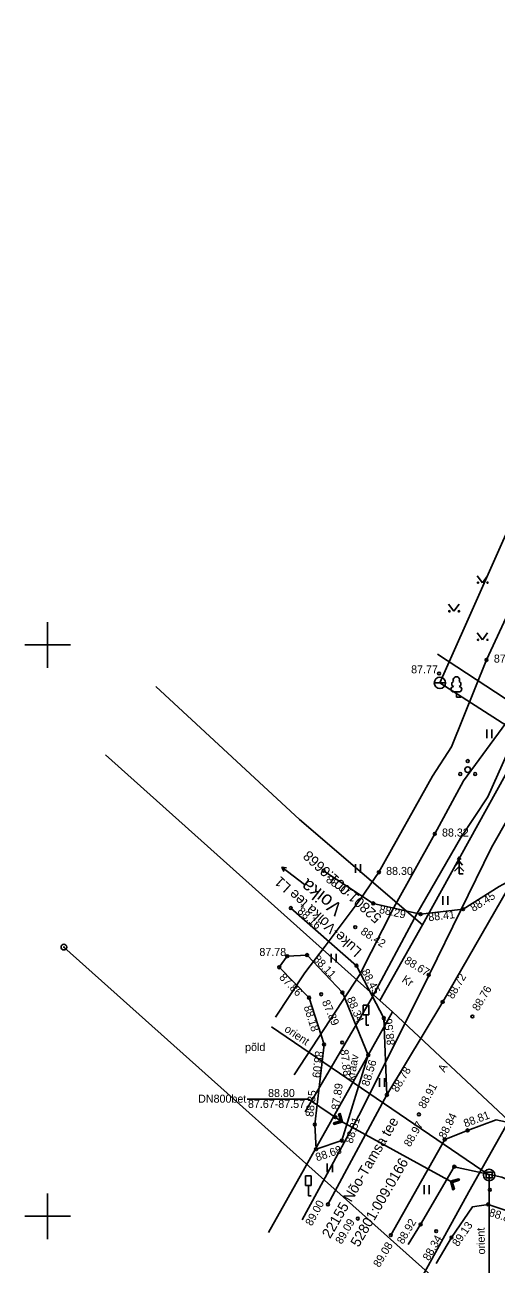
# Model space of a CAD drawing. Extents: x 648748 to 649126, y 6457789 to 6458252.
# Drawn here: x 648748 to 648789.3, y 6457945.8 to 6458054.3 of the extents above; entities that cross this region are included whole.
import ezdxf

# ---------------------------------------------------------------- set-up
doc = ezdxf.new("R2010")
doc.units = 0
for name, color, linetype in [('DKAEV', 7, 'Continuous'), ('DTRASS', 7, 'Continuous'), ('HALJASTUS', 7, 'Continuous'), ('KORGUS-EH2000', 7, 'Continuous'), ('KPOHULIIN', 7, 'Continuous'), ('LIIKLUS', 7, 'Continuous'), ('PIIR', 7, 'Continuous'), ('POST', 7, 'Continuous'), ('PUU', 7, 'Continuous'), ('SITRASS', 7, 'Continuous'), ('TEE', 7, 'Continuous'), ('TRUUP', 7, 'Continuous'), ('VEEKOGU', 7, 'Continuous'), ('VKAEV', 7, 'Continuous'), ('VORK', 7, 'Continuous'), ('VTRASS', 7, 'Continuous')]:
    doc.layers.add(name, color=color, linetype=linetype)

msp = doc.modelspace()

# ---------------------------------------------------------------- linework, layer by layer
at = {"layer": 'DKAEV'}
for p, q in [((648788.39, 6457953.36), (648788.39, 6457953.86)), ((648788.39, 6457953.86), (648788.89, 6457953.86)), ((648788.89, 6457953.36), (648788.39, 6457953.36)), ((648788.89, 6457953.86), (648788.89, 6457953.36))]:
    msp.add_line(p, q, dxfattribs=at)
msp.add_circle((648788.64, 6457953.61), 0.5, dxfattribs=at)
at = {"layer": 'DTRASS'}
for q in [(648769.6, 6457966.59), (648788.64, 6457943.27)]:
    msp.add_line((648788.64, 6457953.61), q, dxfattribs=at)
at = {"layer": 'HALJASTUS'}
for p, q in [((648787.59, 6458006.05), (648788.06, 6458005.44)), ((648788.06, 6458005.44), (648788.5, 6458006.05)), ((648785.09, 6458003.55), (648785.56, 6458002.94)), ((648785.56, 6458002.94), (648786, 6458003.55)), ((648787.59, 6458001.05), (648788.06, 6458000.44)), ((648788.06, 6458000.44), (648788.5, 6458001.05)), ((648784.11, 6457999.19), (648796.89, 6457990.82)), ((648788.42, 6457992.59), (648788.42, 6457991.83)), ((648788.87, 6457992.59), (648788.87, 6457991.83)), ((648776.93, 6457980.82), (648776.93, 6457980.06)), ((648777.39, 6457980.82), (648777.39, 6457980.06)), ((648784.58, 6457978.02), (648784.58, 6457977.26)), ((648785.03, 6457978.02), (648785.03, 6457977.26)), ((648774.81, 6457972.96), (648774.81, 6457972.2)), ((648775.26, 6457972.96), (648775.26, 6457972.2)), ((648779.03, 6457962.1), (648779.03, 6457961.34)), ((648779.49, 6457962.1), (648779.49, 6457961.34)), ((648774.46, 6457954.62), (648774.46, 6457953.86)), ((648774.92, 6457954.62), (648774.92, 6457953.86)), ((648782.95, 6457952.71), (648782.95, 6457951.95)), ((648783.4, 6457952.71), (648783.4, 6457951.95))]:
    msp.add_line(p, q, dxfattribs=at)
for centre in [(648787.66, 6458005.44), (648788.49, 6458005.44), (648785.16, 6458002.94), (648785.99, 6458002.94), (648787.66, 6458000.44), (648788.49, 6458000.44)]:
    msp.add_circle(centre, 0.055, dxfattribs=at)
at = {"layer": 'KORGUS-EH2000'}
for centre in [(648788.41, 6457998.68), (648784.25, 6457997.49), (648783.88, 6457983.46), (648774.15, 6457980.24), (648778.99, 6457980.1), (648778.5, 6457977.38), (648771.28, 6457976.97), (648782.64, 6457976.44), (648786.35, 6457976.88), (648776.92, 6457975.3), (648770.97, 6457972.76), (648772.7, 6457972.86), (648770.27, 6457971.79), (648777.03, 6457971.93), (648783.35, 6457971.12), (648775.79, 6457969.57), (648772.88, 6457969.13), (648773.94, 6457969.43), (648784.57, 6457968.76), (648779.42, 6457967.35), (648787.17, 6457967.48), (648775.77, 6457965.21), (648774.19, 6457965.03), (648778.06, 6457964.11), (648779.69, 6457960.62), (648775.19, 6457958.67), (648782.49, 6457958.92), (648773.38, 6457958.02), (648775.74, 6457956.62), (648784.75, 6457956.72), (648786.75, 6457957.52), (648773.49, 6457955.87), (648785.59, 6457954.34), (648788.7, 6457952.31), (648774.53, 6457951.04), (648788.55, 6457951.04), (648777.14, 6457949.8), (648782.64, 6457949.28), (648780.03, 6457948.35), (648784, 6457948.7), (648785.34, 6457948.14)]:
    msp.add_circle(centre, 0.125, dxfattribs=at)
at = {"layer": 'KPOHULIIN'}
msp.add_line((648751.42, 6457973.56), (648811.64, 6457919.76), dxfattribs=at)
at = {"layer": 'LIIKLUS'}
for points in [[(648777.62, 6457968.48), (648777.62, 6457967.63)], [(648778.12, 6457968.48), (648777.62, 6457968.48)], [(648778.12, 6457967.63), (648777.62, 6457967.63)], [(648777.87, 6457967.63), (648777.87, 6457966.73)], [(648778.12, 6457968.48), (648778.12, 6457967.63)], [(648778.12, 6457966.73), (648777.87, 6457966.73)], [(648772.57, 6457953.54), (648772.57, 6457952.69)], [(648773.07, 6457953.54), (648772.57, 6457953.54)], [(648773.07, 6457953.54), (648773.07, 6457952.69)], [(648773.07, 6457952.69), (648772.57, 6457952.69)], [(648772.82, 6457952.69), (648772.82, 6457951.79)], [(648773.07, 6457951.79), (648772.82, 6457951.79)]]:
    msp.add_lwpolyline(points, dxfattribs=at)
at = {"layer": 'PIIR'}
for p, q in [((648772.05, 6457984.72), (648759.46, 6457996.37)), ((648793.25, 6457994.41), (648782.79, 6457975.49)), ((648779.08, 6457968.88), (648755.06, 6457990.39)), ((648782.79, 6457975.49), (648772.05, 6457984.72)), ((648779.08, 6457968.88), (648782.79, 6457975.49)), ((648780.18, 6457967.9), (648779.08, 6457968.88)), ((648769.34, 6457948.58), (648780.18, 6457967.9)), ((648790.36, 6457958.35), (648780.18, 6457967.9)), ((648786.87, 6457952.13), (648790.36, 6457958.35)), ((648778.84, 6457937.61), (648786.87, 6457952.13))]:
    msp.add_line(p, q, dxfattribs=at)
at = {"layer": 'POST'}
for radius in [0.25, 0.0234]:
    msp.add_circle((648751.42, 6457973.56), radius, dxfattribs=at)
at = {"layer": 'PUU'}
for p, q in [((648786.01, 6457995.88), (648785.53, 6457995.88)), ((648785.77, 6457995.41), (648785.77, 6457995.88)), ((648786.15, 6457995.41), (648785.77, 6457995.41)), ((648786.01, 6457980.61), (648785.61, 6457980.21)), ((648786.01, 6457981.06), (648785.71, 6457980.71)), ((648786.01, 6457981.46), (648785.86, 6457981.21)), ((648786.16, 6457981.21), (648786.01, 6457981.46)), ((648786.01, 6457981.46), (648786.01, 6457979.96)), ((648786.31, 6457980.71), (648786.01, 6457981.06)), ((648786.41, 6457980.21), (648786.01, 6457980.61)), ((648786.37, 6457979.96), (648786.01, 6457979.96))]:
    msp.add_line(p, q, dxfattribs=at)
for centre, radius in [((648786.76, 6457989.08), 0.25), ((648786.76, 6457989.83), 0.125), ((648786.11, 6457988.7), 0.125), ((648787.41, 6457988.7), 0.125)]:
    msp.add_circle(centre, radius, dxfattribs=at)
for centre, radius, start, end in [((648785.6, 6457996.58), 0.233, 109.022, 253.142), ((648785.77, 6457996.93), 0.277, 332.58, 207.42), ((648785.94, 6457996.58), 0.233, 286.851, 70.986), ((648785.53, 6457996.12), 0.238, 90.002, 269.395), ((648786, 6457996.12), 0.238, 270.605, 89.998)]:
    msp.add_arc(centre, radius, start, end, dxfattribs=at)
at = {"layer": 'SITRASS'}
for points in [[(648838.18, 6458075.61), (648836.35, 6458076.52), (648834.03, 6458074.85), (648828.84, 6458070.08), (648823.37, 6458063.8), (648815.04, 6458050.91), (648808.67, 6458038.59), (648805.57, 6458032.71), (648798.85, 6458019.32), (648793.36, 6458009.37), (648788.41, 6457998.68), (648785.35, 6457991.07), (648783.69, 6457988.51), (648778.99, 6457980.1), (648777.34, 6457977.72), (648774.3, 6457973.65), (648772.51, 6457971.29), (648769.94, 6457967.43)], [(648840.7, 6458076.04), (648840.21, 6458074.52), (648835.99, 6458066.48), (648829.45, 6458054.74), (648823.39, 6458043.34), (648816.2, 6458031.07), (648810.1, 6458020.65), (648803.23, 6458008.29), (648797.37, 6457997.81), (648791.83, 6457987.5), (648788.85, 6457982.27), (648783.41, 6457971.18), (648777.4, 6457959.15), (648772.28, 6457949.69)], [(648771.56, 6457962.37), (648777.32, 6457971.17), (648780.29, 6457977.01), (648783.88, 6457983.46), (648786.39, 6457988.11), (648790.09, 6457993.16), (648795.13, 6458001.6), (648799.02, 6458008.18), (648807.6, 6458023.19), (648816.81, 6458039.67), (648823.72, 6458052.09), (648829.84, 6458063.34), (648833.46, 6458070), (648835.84, 6458074.5), (648836.93, 6458074.75), (648838.18, 6458075.61)], [(648772.53, 6457959.14), (648778.31, 6457968.99), (648782.3, 6457976.47), (648786.13, 6457983.09), (648788.53, 6457986.69), (648790.27, 6457990.62), (648793.73, 6457995.08), (648800.38, 6458006.93), (648808.98, 6458022.03), (648818.07, 6458038.43), (648824.93, 6458050.59), (648831.03, 6458061.41), (648834.79, 6458068.89), (648838.18, 6458075.61), (648839.48, 6458073.45), (648841.57, 6458071.26), (648846.87, 6458065.92), (648848.75, 6458063.39)]]:
    msp.add_lwpolyline(points, dxfattribs=at)
at = {"layer": 'TEE'}
for p in [(648772.48, 6457979.03), (648770.66, 6457980.18), (648770.91, 6457980.5)]:
    msp.add_line(p, (648770.5, 6457980.56), dxfattribs=at)
for points in [[(648844.3, 6458074.59), (648841.57, 6458069.96), (648835.93, 6458060.04), (648830.01, 6458049.68), (648824.32, 6458039.38), (648818.36, 6458028.96), (648812.61, 6458018.63), (648806.66, 6458008.28), (648800.57, 6457997.47), (648794.38, 6457986.28), (648790.81, 6457979.57), (648784.57, 6457968.76), (648779.69, 6457960.62), (648774.53, 6457951.04)], [(648790.81, 6457979.57), (648789.51, 6457978.85), (648786.35, 6457976.88), (648782.64, 6457976.44), (648778.5, 6457977.38), (648774.15, 6457980.24)], [(648771.28, 6457976.97), (648777.03, 6457971.93), (648779.42, 6457967.35), (648779.69, 6457960.62)], [(648812.41, 6457940.36), (648808.54, 6457944.02), (648800.05, 6457951.25), (648791.29, 6457958.01), (648789.24, 6457958.44), (648786.75, 6457957.52), (648784.75, 6457956.72)], [(648780.03, 6457948.35), (648784.75, 6457956.72)]]:
    msp.add_lwpolyline(points, dxfattribs=at)
at = {"layer": 'TRUUP'}
for p, q in [((648775.45, 6457958.96), (648775.59, 6457959)), ((648775.63, 6457958.35), (648775.45, 6457958.96)), ((648775.46, 6457958.96), (648775.61, 6457958.93)), ((648775.46, 6457958.93), (648775.62, 6457958.9)), ((648775.47, 6457958.9), (648775.63, 6457958.87)), ((648775.48, 6457958.88), (648775.64, 6457958.85)), ((648775.49, 6457958.85), (648775.64, 6457958.82)), ((648775.5, 6457958.98), (648775.61, 6457958.96)), ((648775.5, 6457958.82), (648775.65, 6457958.79)), ((648775.5, 6457958.8), (648775.66, 6457958.77)), ((648775.72, 6457958.3), (648775.52, 6457958.98)), ((648775.55, 6457958.99), (648775.6, 6457958.98)), ((648775.81, 6457958.26), (648775.59, 6457959)), ((648775.02, 6457958.17), (648775.63, 6457958.35)), ((648775.02, 6457958.17), (648775.06, 6457958.04)), ((648775.02, 6457958.17), (648775.33, 6457958.12)), ((648775.03, 6457958.15), (648775.28, 6457958.1)), ((648775.04, 6457958.11), (648775.72, 6457958.3)), ((648775.04, 6457958.12), (648775.22, 6457958.09)), ((648775.05, 6457958.09), (648775.17, 6457958.07)), ((648775.05, 6457958.07), (648775.12, 6457958.05)), ((648775.06, 6457958.04), (648775.81, 6457958.26)), ((648775.07, 6457958.19), (648775.38, 6457958.13)), ((648775.13, 6457958.2), (648775.44, 6457958.15)), ((648775.18, 6457958.22), (648775.49, 6457958.16)), ((648775.23, 6457958.24), (648775.54, 6457958.18)), ((648775.29, 6457958.25), (648775.6, 6457958.19)), ((648775.34, 6457958.27), (648775.65, 6457958.21)), ((648775.39, 6457958.28), (648775.7, 6457958.22)), ((648775.45, 6457958.3), (648775.76, 6457958.24)), ((648775.5, 6457958.31), (648775.81, 6457958.26)), ((648775.51, 6457958.77), (648775.67, 6457958.74)), ((648775.52, 6457958.74), (648775.68, 6457958.71)), ((648775.53, 6457958.72), (648775.68, 6457958.69)), ((648775.53, 6457958.69), (648775.69, 6457958.66)), ((648775.54, 6457958.66), (648775.7, 6457958.63)), ((648775.55, 6457958.63), (648775.71, 6457958.61)), ((648775.55, 6457958.33), (648775.8, 6457958.28)), ((648775.56, 6457958.61), (648775.72, 6457958.58)), ((648775.57, 6457958.58), (648775.72, 6457958.55)), ((648775.57, 6457958.55), (648775.73, 6457958.52)), ((648775.58, 6457958.53), (648775.74, 6457958.5)), ((648775.59, 6457958.5), (648775.75, 6457958.47)), ((648775.6, 6457958.47), (648775.75, 6457958.44)), ((648775.6, 6457958.45), (648775.76, 6457958.42)), ((648775.61, 6457958.42), (648775.77, 6457958.39)), ((648775.61, 6457958.34), (648775.79, 6457958.31)), ((648775.62, 6457958.39), (648775.78, 6457958.36)), ((648775.63, 6457958.37), (648775.79, 6457958.34)), ((648775.72, 6457958.3), (648785.34, 6457953.02)), ((648785.99, 6457953.29), (648785.25, 6457953.07)), ((648785.25, 6457953.07), (648785.46, 6457952.32)), ((648785.56, 6457953.01), (648785.25, 6457953.07)), ((648785.5, 6457953), (648785.26, 6457953.04)), ((648785.45, 6457952.98), (648785.26, 6457953.02)), ((648785.43, 6457952.96), (648785.27, 6457952.99)), ((648785.44, 6457952.93), (648785.28, 6457952.96)), ((648785.44, 6457952.91), (648785.29, 6457952.93)), ((648785.45, 6457952.88), (648785.29, 6457952.91)), ((648785.61, 6457953.03), (648785.3, 6457953.08)), ((648785.46, 6457952.85), (648785.3, 6457952.88)), ((648785.47, 6457952.82), (648785.31, 6457952.85)), ((648785.47, 6457952.8), (648785.32, 6457952.83)), ((648785.48, 6457952.77), (648785.33, 6457952.8)), ((648785.49, 6457952.74), (648785.33, 6457952.77)), ((648786.01, 6457953.22), (648785.34, 6457953.02)), ((648785.34, 6457953.02), (648785.53, 6457952.34)), ((648785.5, 6457952.72), (648785.34, 6457952.75)), ((648785.66, 6457953.04), (648785.35, 6457953.1)), ((648785.51, 6457952.69), (648785.35, 6457952.72)), ((648785.51, 6457952.66), (648785.36, 6457952.69)), ((648785.52, 6457952.64), (648785.36, 6457952.67)), ((648785.53, 6457952.61), (648785.37, 6457952.64)), ((648785.54, 6457952.58), (648785.38, 6457952.61)), ((648785.55, 6457952.56), (648785.39, 6457952.59)), ((648785.55, 6457952.53), (648785.4, 6457952.56)), ((648785.56, 6457952.5), (648785.4, 6457952.53)), ((648785.72, 6457953.06), (648785.41, 6457953.12)), ((648785.57, 6457952.48), (648785.41, 6457952.5)), ((648786.03, 6457953.15), (648785.42, 6457952.97)), ((648785.42, 6457952.97), (648785.6, 6457952.36)), ((648785.58, 6457952.45), (648785.42, 6457952.48)), ((648785.58, 6457952.42), (648785.43, 6457952.45)), ((648785.59, 6457952.39), (648785.43, 6457952.42)), ((648785.6, 6457952.37), (648785.44, 6457952.4)), ((648785.56, 6457952.35), (648785.45, 6457952.37)), ((648785.77, 6457953.07), (648785.46, 6457953.13)), ((648785.6, 6457952.36), (648785.46, 6457952.32)), ((648785.51, 6457952.33), (648785.46, 6457952.34)), ((648785.82, 6457953.09), (648785.51, 6457953.15)), ((648785.88, 6457953.1), (648785.57, 6457953.16)), ((648785.93, 6457953.12), (648785.62, 6457953.18)), ((648785.98, 6457953.14), (648785.67, 6457953.19)), ((648786.03, 6457953.15), (648785.73, 6457953.21)), ((648786.03, 6457953.18), (648785.78, 6457953.22)), ((648786.02, 6457953.21), (648785.83, 6457953.24)), ((648786.01, 6457953.23), (648785.89, 6457953.26)), ((648786, 6457953.26), (648785.94, 6457953.27)), ((648786.03, 6457953.15), (648785.99, 6457953.29))]:
    msp.add_line(p, q, dxfattribs=at)
msp.add_lwpolyline([(648775.72, 6457958.3), (648772.84, 6457960.24), (648767.47, 6457960.24)], dxfattribs=at)
at = {"layer": 'VEEKOGU'}
for points in [[(648770.27, 6457971.79), (648770.97, 6457972.76), (648772.7, 6457972.86), (648775.79, 6457969.57), (648778.06, 6457964.11), (648775.74, 6457956.62), (648773.49, 6457955.87), (648773.38, 6457958.02), (648774.19, 6457965.03), (648772.88, 6457969.13), (648770.27, 6457971.79)], [(648781.55, 6457947.52), (648782.64, 6457949.28), (648785.59, 6457954.34), (648789.76, 6457953.43), (648797.17, 6457950.22), (648804.11, 6457946.85), (648805.16, 6457945.52), (648804.61, 6457945.14), (648796.89, 6457948.27), (648788.55, 6457951.04), (648787.17, 6457950.82), (648785.34, 6457948.14), (648784.01, 6457945.88)]]:
    msp.add_lwpolyline(points, dxfattribs=at)
at = {"layer": 'VKAEV'}
msp.add_line((648783.83, 6457996.67), (648784.83, 6457996.67), dxfattribs=at)
msp.add_circle((648784.33, 6457996.67), 0.5, dxfattribs=at)
at = {"layer": 'VORK'}
for p, q in [((648750, 6458002), (648750, 6457998)), ((648748, 6458000), (648752, 6458000)), ((648750, 6457952), (648750, 6457948)), ((648748, 6457950), (648752, 6457950))]:
    msp.add_line(p, q, dxfattribs=at)
at = {"layer": 'VTRASS'}
for p, q in [((648818.87, 6458074.61), (648784.33, 6457996.67)), ((648784.33, 6457996.67), (648805, 6457983.36))]:
    msp.add_line(p, q, dxfattribs=at)

# ---------------------------------------------------------------- texts
at = {"layer": 'DTRASS'}
for rotation, p in [(326.1395, (648770.66, 6457966.23)), (91.3542, (648788.29, 6457946.67))]:
    msp.add_text('orient', height=0.7, rotation=rotation, dxfattribs=at).set_placement(p)
at = {"layer": 'HALJASTUS'}
msp.add_text('põld', height=0.7, dxfattribs=at).set_placement((648767.28, 6457964.46))
at = {"layer": 'KORGUS-EH2000'}
for s, p in [(' 87.92', (648788.79, 6457998.45)), (' 87.77', (648781.55, 6457997.51)), (' 88.32', (648784.25, 6457983.23)), (' 88.30', (648779.36, 6457979.87)), (' 87.78', (648768.27, 6457972.78))]:
    msp.add_text(s, height=0.7, dxfattribs=at).set_placement(p)
for s, rotation, p in [(' 88.07', 326.6849, (648774.08, 6457979.45)), (' 88.45', 32.0568, (648787.04, 6457976.48)), (' 88.29', 347.309, (648778.71, 6457976.61)), (' 88.16', 318.7714, (648771.61, 6457976.78)), (' 88.41', 6.637, (648783.09, 6457975.79)), (' 88.42', 327.0037, (648777.11, 6457974.9)), (' 88.11', 313.2448, (648773.02, 6457972.65)), (' 88.67', 328.3177, (648780.93, 6457972.34)), (' 87.86', 314.3889, (648770.03, 6457971.04)), (' 88.45', 297.6142, (648777.32, 6457971.66)), (' 88.72', 60.0156, (648785.36, 6457968.73)), (' 88.76', 59.3075, (648787.56, 6457967.68)), (' 87.89', 293.3902, (648773.88, 6457969)), (' 88.34', 292.5801, (648776.07, 6457969.29)), (' 88.18', 287.8038, (648772.32, 6457968.57)), (' 88.56', 96.5778, (648780.43, 6457964.75)), (' 88.09', 263.4004, (648773.45, 6457964.75)), (' 87.88', 276.7467, (648775.58, 6457964.82)), (' 88.56', 72.7667, (648778.03, 6457961.08)), (' 88.78', 59.0617, (648780.49, 6457960.58)), (' 88.35', 83.4004, (648773.22, 6457958.41)), (' 87.89', 81.8215, (648775.47, 6457959.01)), (' 88.91', 61.3185, (648782.87, 6457959.13)), (' 88.84', 63.0333, (648784.66, 6457956.49)), (' 88.81', 20.3207, (648786.31, 6457957.68)), (' 88.81', 72.7667, (648776.59, 6457956.07)), (' 88.97', 59.8445, (648781.59, 6457955.79)), (' 88.68', 18.5132, (648773.33, 6457954.72)), (' 89.00', 61.6686, (648772.99, 6457948.87)), (' 88.88', 341.5972, (648788.32, 6457950.14)), (' 89.09', 59.4201, (648775.59, 6457947.28)), (' 88.92', 59.7046, (648780.98, 6457947.28)), (' 89.13', 55.7282, (648785.77, 6457947.08)), (' 88.34', 60.2812, (648783.25, 6457945.83)), (' 89.08', 58.9436, (648778.9, 6457945.25))]:
    msp.add_text(s, height=0.7, rotation=rotation, dxfattribs=at).set_placement(p)
at = {"layer": 'PIIR'}
for s, rotation, p in [('52801:001:0668', 137.7085, (648779.3, 6457976.22)), ('Luke-Voika tee L1', 137.7085, (648777.55, 6457973.28)), ('22155 Nõo-Tamsa tee', 59.7525, (648774.72, 6457948)), ('52801:009:0166', 59.7525, (648777.22, 6457947.24))]:
    msp.add_text(s, height=0.9, rotation=rotation, dxfattribs=at).set_placement(p)
at = {"layer": 'TEE'}
for s, height, rotation, p in [('Voika ', 1.2, 141.9672, (648775.9, 6457977.14)), ('Kr', 0.7, 327.0519, (648780.94, 6457970.56)), ('A', 0.7, 62.2738, (648784.73, 6457962.55))]:
    msp.add_text(s, height=height, rotation=rotation, dxfattribs=at).set_placement(p)
at = {"layer": 'TRUUP'}
for s, p in [('88.80', (648769.29, 6457960.44)), ('DN800bet', (648763.17, 6457959.94)), ('87.67-87.57', (648767.53, 6457959.48))]:
    msp.add_text(s, height=0.7, dxfattribs=at).set_placement(p)
at = {"layer": 'VEEKOGU'}
msp.add_text('kraav', height=0.7, rotation=80.7645, dxfattribs=at).set_placement((648776.85, 6457961.85))

doc.saveas('drawing.dxf')
